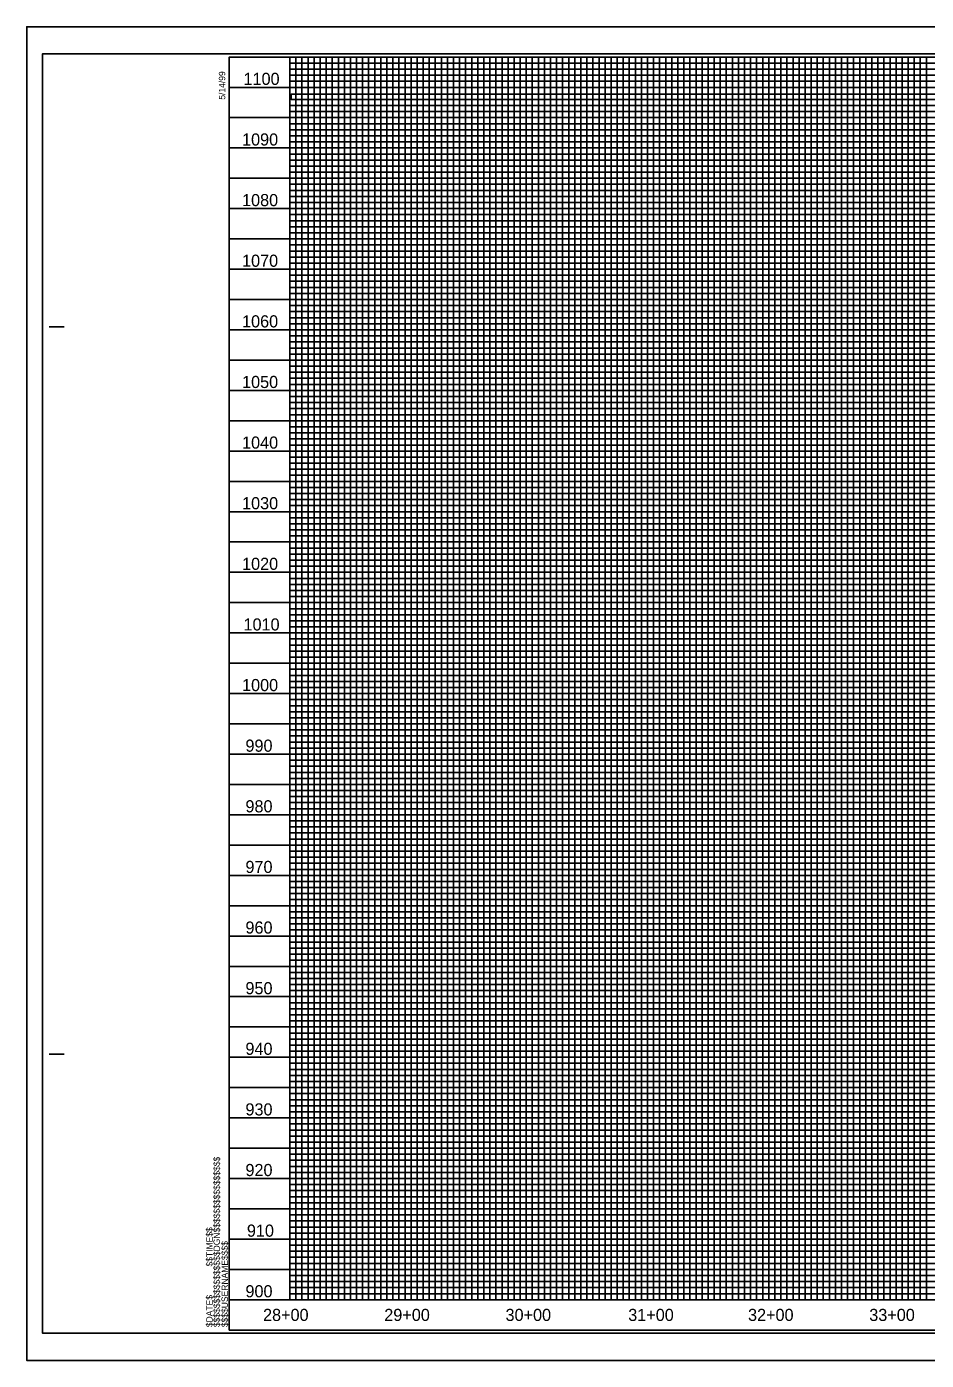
# Model space of a CAD drawing. Extents: x 1262239 to 1263984, y 747221 to 748321.
# Drawn here: x 1262239 to 1262981, y 747221 to 748321 of the extents above; entities that cross this region are included whole.
import ezdxf

# ---------------------------------------------------------------- set-up
doc = ezdxf.new("R2010")
doc.units = 0
for name, color, linetype in [('Pattern 1', 7, 'Continuous'), ('Pattern 2', 7, 'Continuous'), ('Prop Drainage Structure Bridge Opening', 7, 'Continuous'), ('Prop Grid Mask', 7, 'Continuous'), ('Prop Horizontal Alignment Curve and Spiral Data', 7, 'Continuous'), ('Prop Paved Shoulder', 7, 'Continuous'), ('Prop PFL Text', 7, 'Continuous'), ('Prop Roadway Bridge', 7, 'Continuous'), ('Prop Terminator CELL', 7, 'Continuous'), ('Prop Vertical Profile Strip Grade', 7, 'Continuous'), ('Prop VPI Label', 7, 'Continuous'), ('Sheet Sticker Exception Certification CELL', 7, 'Continuous')]:
    doc.layers.add(name, color=color, linetype=linetype)

msp = doc.modelspace()

# ---------------------------------------------------------------- linework, layer by layer
at = {"layer": 'Pattern 1'}
for points in [[(1262405.8, 748295.7), (1262455.8, 748295.7), (1262455.8, 747270.7), (1262505.8, 747270.7), (1262505.8, 748295.7), (1262555.8, 748295.7), (1262555.8, 747270.7), (1262605.8, 747270.7), (1262605.8, 748295.7), (1262655.8, 748295.7), (1262655.8, 747270.7), (1262705.8, 747270.7), (1262705.8, 748295.7), (1262755.8, 748295.7), (1262755.8, 747270.7), (1262805.8, 747270.7), (1262805.8, 748295.7), (1262855.8, 748295.7), (1262855.8, 747270.7), (1262905.8, 747270.7), (1262905.8, 748295.7), (1262955.8, 748295.7), (1262955.8, 747270.7), (1263005.8, 747270.7)], [(1263705.7, 748220.7), (1262405.9, 748220.7), (1262405.9, 748270.7), (1263605.8, 748270.7)], [(1263905.8, 748120.7), (1262405.8, 748120.7), (1262405.8, 748170.7), (1263705.7, 748170.7)], [(1263905.8, 748020.7), (1262405.8, 748020.7), (1262405.8, 748070.7), (1263905.8, 748070.7)], [(1263905.8, 747920.7), (1262405.8, 747920.7), (1262405.8, 747970.7), (1263905.8, 747970.7)], [(1263905.8, 747820.7), (1262405.8, 747820.7), (1262405.8, 747870.7), (1263905.8, 747870.7)], [(1263905.8, 747720.7), (1262405.8, 747720.7), (1262405.8, 747770.7), (1263905.8, 747770.7)], [(1263905.8, 747620.7), (1262405.8, 747620.7), (1262405.8, 747670.7), (1263905.8, 747670.7)], [(1263905.8, 747520.7), (1262405.8, 747520.7), (1262405.8, 747570.7), (1263905.8, 747570.7)], [(1263905.8, 747420.7), (1262405.8, 747420.7), (1262405.8, 747470.7), (1263905.8, 747470.7)], [(1263905.8, 747320.7), (1262405.8, 747320.7), (1262405.8, 747370.7), (1263905.8, 747370.7)]]:
    msp.add_lwpolyline(points, dxfattribs=at)
at = {"layer": 'Pattern 2'}
for points in [[(1262480.8, 747270.7), (1262480.8, 748295.7), (1262530.8, 748295.7), (1262530.8, 747270.7), (1262580.8, 747270.7), (1262580.8, 748295.7), (1262630.8, 748295.7), (1262630.8, 747270.7), (1262680.8, 747270.7), (1262680.8, 748295.7), (1262730.8, 748295.7), (1262730.8, 747270.7), (1262780.8, 747270.7), (1262780.8, 748295.7), (1262830.8, 748295.7), (1262830.8, 747270.7), (1262880.8, 747270.7), (1262880.8, 748295.7), (1262930.8, 748295.7), (1262930.8, 747270.7), (1262980.8, 747270.7), (1262980.8, 748295.7), (1263030.8, 748295.7)], [(1262405.8, 748245.7), (1263705.7, 748245.7)], [(1263705.7, 748195.7), (1262405.8, 748195.7), (1262405.8, 748145.7), (1263705.7, 748145.7)], [(1263905.8, 748095.7), (1262405.8, 748095.7), (1262405.8, 748045.7), (1263905.8, 748045.7)], [(1263905.8, 747995.7), (1262405.8, 747995.7), (1262405.8, 747945.7), (1263905.8, 747945.7)], [(1263905.8, 747895.7), (1262405.8, 747895.7), (1262405.8, 747845.7), (1263905.8, 747845.7)], [(1263905.8, 747795.7), (1262405.8, 747795.7), (1262405.8, 747745.7), (1263905.8, 747745.7)], [(1263905.8, 747695.7), (1262405.8, 747695.7), (1262405.8, 747645.7), (1263905.8, 747645.7)], [(1263905.8, 747595.7), (1262405.8, 747595.7), (1262405.8, 747545.7), (1263905.8, 747545.7)], [(1263905.8, 747495.7), (1262405.8, 747495.7), (1262405.8, 747445.7), (1263905.8, 747445.7)], [(1263905.8, 747395.7), (1262405.8, 747395.7), (1262405.8, 747345.7), (1263905.8, 747345.7)], [(1263905.8, 747295.7), (1262405.8, 747295.7)]]:
    msp.add_lwpolyline(points, dxfattribs=at)
at = {"layer": 'Prop Drainage Structure Bridge Opening'}
for p, q in [((1263922.8, 748320.7), (1262238.8, 748320.7)), ((1262238.8, 748320.7), (1262238.8, 747220.7)), ((1262238.8, 747220.7), (1263922.8, 747220.7))]:
    msp.add_line(p, q, dxfattribs=at)
at = {"layer": 'Prop Grid Mask'}
msp.add_lwpolyline([(1262455.8, 748295.7), (1263705.7, 748295.7), (1263705.7, 748134.7), (1263855.8, 748134.7), (1263855.8, 747270.7), (1262455.8, 747270.7)], close=True, dxfattribs=at)
at = {"layer": 'Prop Paved Shoulder'}
for p, q in [((1262257.3, 748073.2), (1262269.8, 748073.2)), ((1262257.3, 747473.2), (1262269.8, 747473.2)), ((1263905.8, 747270.7), (1262405.8, 747270.7)), ((1262405.8, 747245.7), (1262405.8, 747245.7)), ((1262405.8, 747245.7), (1262405.8, 747245.7)), ((1262405.8, 747245.7), (1262405.8, 747245.7)), ((1262405.8, 747245.7), (1262405.8, 747245.7)), ((1262405.8, 747245.7), (1262405.8, 747245.7)), ((1262405.8, 747245.7), (1262405.8, 747245.7))]:
    msp.add_line(p, q, dxfattribs=at)
msp.add_lwpolyline([(1263905.8, 748295.7), (1262405.8, 748295.7), (1262405.8, 747245.7), (1263905.8, 747245.7)], close=True, dxfattribs=at)
msp.add_lwpolyline([(1262443.3, 747245.7), (1262443.3, 747245.7)], dxfattribs=at)
at = {"layer": 'Prop PFL Text'}
for p, q in [((1262455.8, 748295.7), (1262455.8, 747270.7)), ((1262505.8, 748295.7), (1262505.8, 747270.7)), ((1262555.8, 748295.7), (1262555.8, 747270.7)), ((1262605.8, 748295.7), (1262605.8, 747270.7)), ((1262655.8, 748295.7), (1262655.8, 747270.7)), ((1262705.8, 748295.7), (1262705.8, 747270.7)), ((1262755.8, 748295.7), (1262755.8, 747270.7)), ((1262805.8, 748295.7), (1262805.8, 747270.7)), ((1262855.8, 748295.7), (1262855.8, 747270.7)), ((1262905.8, 748295.7), (1262905.8, 747270.7)), ((1262955.8, 748295.7), (1262955.8, 747270.7)), ((1262405.8, 748270.7), (1263605.8, 748270.7)), ((1262405.8, 748220.7), (1263705.7, 748220.7)), ((1262405.8, 748170.7), (1263705.7, 748170.7)), ((1262405.8, 748120.7), (1263905.8, 748120.7)), ((1262405.8, 748070.7), (1263905.8, 748070.7)), ((1262405.8, 748020.7), (1263905.8, 748020.7)), ((1262405.8, 747970.7), (1263905.8, 747970.7)), ((1262405.8, 747920.7), (1263905.8, 747920.7)), ((1262405.8, 747870.7), (1263905.8, 747870.7)), ((1262405.8, 747820.7), (1263905.8, 747820.7)), ((1262405.8, 747770.7), (1263905.8, 747770.7)), ((1262405.8, 747720.7), (1263905.8, 747720.7)), ((1262405.8, 747670.7), (1263905.8, 747670.7)), ((1262405.8, 747620.7), (1263905.8, 747620.7)), ((1262405.8, 747570.7), (1263905.8, 747570.7)), ((1262405.8, 747520.7), (1263905.8, 747520.7)), ((1262405.8, 747470.7), (1263905.8, 747470.7)), ((1262405.8, 747420.7), (1263905.8, 747420.7)), ((1262405.8, 747370.7), (1263905.8, 747370.7)), ((1262405.8, 747320.7), (1263905.8, 747320.7))]:
    msp.add_line(p, q, dxfattribs=at)
at = {"layer": 'Prop Roadway Bridge'}
msp.add_line((1262405.8, 747245.7), (1262405.8, 747245.7), dxfattribs=at)
at = {"layer": 'Prop Terminator CELL'}
msp.add_lwpolyline([(1263918.3, 748298.3), (1262251.8, 748298.3), (1262251.8, 747243.2), (1263918.3, 747243.2)], close=True, dxfattribs=at)
at = {"layer": 'Prop VPI Label'}
msp.add_lwpolyline([(1263922.8, 748320.7), (1262238.8, 748320.7), (1262238.8, 747220.7), (1263922.8, 747220.7)], close=True, dxfattribs=at)
at = {"layer": 'Sheet Sticker Exception Certification CELL'}
for p, q in [((1263855.8, 748115.7), (1262455.8, 748115.7)), ((1262455.8, 748115.7), (1262455.8, 748110.7)), ((1262455.8, 748110.7), (1263855.8, 748110.7)), ((1263855.8, 748090.7), (1262455.8, 748090.7))]:
    msp.add_line(p, q, dxfattribs=at)
for points in [[(1262460.8, 748295.7), (1262465.8, 748295.7), (1262470.8, 748295.7), (1262475.8, 748295.7), (1262485.8, 748295.7), (1262452.7, 748295.7), (1262457.7, 748295.7), (1262415.8, 748295.7), (1262420.8, 748295.7), (1262425.8, 748295.7), (1262435.8, 748295.7), (1262440.8, 748295.7), (1262445.8, 748295.7), (1262450.8, 748295.7), (1262460.8, 748295.7), (1262460.8, 747270.7), (1262465.8, 747270.7), (1262465.8, 748295.7), (1262470.8, 748295.7), (1262470.8, 747270.7), (1262475.8, 747270.7), (1262475.8, 748295.7), (1262485.8, 748295.7), (1262485.8, 747270.7), (1262490.8, 747270.7), (1262490.8, 748295.7), (1262495.8, 748295.7), (1262495.8, 747270.7), (1262500.8, 747270.7), (1262500.8, 748295.7), (1262510.8, 748295.7), (1262510.8, 747270.7), (1262515.8, 747270.7), (1262515.8, 748295.7), (1262520.8, 748295.7), (1262520.8, 747270.7), (1262525.8, 747270.7), (1262525.8, 748295.7), (1262535.8, 748295.7), (1262535.8, 747270.7), (1262540.8, 747270.7), (1262540.8, 748295.7), (1262545.8, 748295.7), (1262545.8, 747270.7), (1262550.8, 747270.7), (1262550.8, 748295.7), (1262560.8, 748295.7), (1262560.8, 747270.7), (1262565.8, 747270.7), (1262565.8, 748295.7), (1262570.8, 748295.7), (1262570.8, 747270.7), (1262575.8, 747270.7), (1262575.8, 748295.7), (1262585.8, 748295.7), (1262585.8, 747270.7), (1262590.8, 747270.7), (1262590.8, 748295.7), (1262595.8, 748295.7), (1262595.8, 747270.7), (1262600.8, 747270.7), (1262600.8, 748295.7), (1262610.8, 748295.7), (1262610.8, 747270.7), (1262615.8, 747270.7), (1262615.8, 748295.7), (1262620.8, 748295.7), (1262620.8, 747270.7)], [(1263605.8, 748290.7), (1262455.8, 748290.7), (1262455.8, 748285.7), (1263605.8, 748285.7)], [(1262620.8, 747270.7), (1262625.8, 747270.7), (1262625.8, 748295.7), (1262635.8, 748295.7), (1262635.8, 747270.7), (1262640.8, 747270.7), (1262640.8, 748295.7), (1262645.8, 748295.7), (1262645.8, 747270.7), (1262650.8, 747270.7), (1262650.8, 748295.7), (1262660.8, 748295.7), (1262660.8, 747270.7), (1262665.8, 747270.7), (1262665.8, 748295.7), (1262665.8, 748295.7), (1262670.8, 748295.7), (1262670.8, 747270.7), (1262675.8, 747270.7), (1262675.8, 748295.7), (1262685.8, 748295.7), (1262685.8, 747270.7), (1262690.8, 747270.7), (1262690.8, 748295.7), (1262695.8, 748295.7), (1262695.8, 747270.7), (1262700.8, 747270.7), (1262700.8, 748295.7), (1262710.8, 748295.7), (1262710.8, 747270.7), (1262715.8, 747270.7), (1262715.8, 748295.7), (1262720.8, 748295.7), (1262720.8, 747270.7), (1262725.8, 747270.7), (1262725.8, 748295.7), (1262735.8, 748295.7), (1262735.8, 747270.7), (1262740.8, 747270.7), (1262740.8, 748295.7), (1262745.8, 748295.7), (1262745.8, 747270.7), (1262750.8, 747270.7), (1262750.8, 748295.7), (1262760.8, 748295.7), (1262760.8, 747270.7), (1262765.8, 747270.7), (1262765.8, 748295.7), (1262770.8, 748295.7), (1262770.8, 747270.7), (1262775.8, 747270.7), (1262775.8, 748295.7), (1262785.8, 748295.7), (1262785.8, 747270.7), (1262800.8, 747270.7), (1262800.8, 748295.7), (1262810.8, 748295.7), (1262810.8, 747270.7), (1262815.8, 747270.7), (1262815.8, 748295.7), (1262820.8, 748295.7), (1262820.8, 747270.7), (1262825.8, 747270.7), (1262825.8, 748295.7), (1262835.8, 748295.7), (1262835.8, 747270.7), (1262840.8, 747270.7), (1262840.8, 748295.7), (1262845.8, 748295.7), (1262845.8, 747270.7), (1262850.8, 747270.7), (1262850.8, 748295.7), (1262860.8, 748295.7), (1262860.8, 747270.7), (1262865.8, 747270.7), (1262865.8, 748295.7), (1262870.8, 748295.7), (1262870.8, 747270.7), (1262875.8, 747270.7), (1262875.8, 748295.7), (1262885.8, 748295.7), (1262885.8, 747270.7), (1262890.8, 747270.7), (1262890.8, 748295.7), (1262895.8, 748295.7), (1262895.8, 747270.7), (1262900.8, 747270.7), (1262900.8, 748295.7), (1262910.8, 748295.7), (1262910.8, 747270.7), (1262915.8, 747270.7), (1262915.8, 748295.7), (1262920.8, 748295.7), (1262920.8, 747270.7), (1262925.8, 747270.7), (1262925.8, 748295.7), (1262935.8, 748295.7), (1262935.8, 747270.7)], [(1262790.8, 748295.7), (1262790.8, 747270.7), (1262795.8, 747270.7), (1262795.8, 748295.7)], [(1262790.8, 748295.1), (1262790.8, 747270.7), (1262795.8, 747270.7), (1262795.8, 748295.1)], [(1262940.8, 748295.7), (1262940.8, 747270.7), (1262945.8, 747270.7), (1262945.8, 748295.7), (1262950.8, 748295.7), (1262950.8, 747270.7), (1262960.8, 747270.7), (1262960.8, 748295.7), (1262965.8, 748295.7), (1262965.8, 747270.7), (1262970.8, 747270.7), (1262970.8, 748295.7), (1262975.8, 748295.7), (1262975.8, 747270.7)], [(1263605.8, 748280.7), (1262455.8, 748280.7), (1262455.8, 748275.7), (1263605.8, 748275.7)], [(1263605.8, 748265), (1262456.8, 748265), (1262456.8, 748260.7), (1263605.8, 748260.7)], [(1263605.8, 748255.7), (1262455.8, 748255.7), (1262455.8, 748250.7), (1263605.8, 748250.7)], [(1263705.7, 748240.7), (1262455.8, 748240.7), (1262455.8, 748235.7), (1263705.7, 748235.7)], [(1263705.7, 748230.7), (1262455.8, 748230.7), (1262455.8, 748225.7), (1263705.7, 748225.7)], [(1263705.7, 748215.7), (1262455.8, 748215.7), (1262455.8, 748210.7), (1263705.7, 748210.7)], [(1263705.7, 748205.7), (1262455.8, 748205.7), (1262455.8, 748200.7), (1263705.7, 748200.7)], [(1263705.7, 748190.7), (1262455.8, 748190.7), (1262455.8, 748185.7), (1263705.7, 748185.7)], [(1263705.7, 748180.7), (1262455.8, 748180.7), (1262455.8, 748175.7), (1263705.7, 748175.7)], [(1263705.7, 748165.7), (1262455.8, 748165.7), (1262455.8, 748160.7), (1263705.7, 748160.7)], [(1263705.7, 748155.7), (1262455.8, 748155.7), (1262455.8, 748155.7), (1262455.8, 748135.7), (1263705.7, 748135.7)], [(1262455.8, 748150.7), (1263705.7, 748150.7)], [(1263705.7, 748140.7), (1262455.8, 748140.7)], [(1263855.8, 748130.7), (1262455.8, 748130.7), (1262455.8, 748125.7), (1263855.8, 748125.7)], [(1263855.8, 748105.7), (1262455.8, 748105.7), (1262455.8, 748100.7), (1263855.8, 748100.7)], [(1263855.8, 748085.7), (1262455.8, 748085.7), (1262455.8, 748080.7), (1263855.8, 748080.7)], [(1263855.8, 748075.7), (1262455.8, 748075.7)], [(1262455.8, 748065.7), (1263855.8, 748065.7)], [(1263855.8, 748060.7), (1262455.8, 748060.7), (1262455.8, 748055.7), (1263855.8, 748055.7)], [(1263855.8, 748050.7), (1262455.8, 748050.7), (1262455.8, 748040.7), (1263855.8, 748040.7)], [(1263855.8, 748035.7), (1262455.8, 748035.7), (1262455.8, 748030.7), (1263855.8, 748030.7)], [(1263855.8, 748025.7), (1262455.8, 748025.7), (1262455.8, 748015.7), (1263855.8, 748015.7)], [(1263855.8, 748010.7), (1262455.8, 748010.7), (1262455.8, 748005.7), (1263855.8, 748005.7)], [(1263855.8, 748000.7), (1262455.8, 748000.7), (1262455.8, 747990.7), (1263855.8, 747990.7)], [(1263855.8, 747985.7), (1262455.8, 747985.7), (1262455.8, 747980.7), (1263855.8, 747980.7)], [(1263855.8, 747975.7), (1262455.8, 747975.7), (1262455.8, 747965.7), (1263855.8, 747965.7)], [(1263855.8, 747960.7), (1262455.8, 747960.7), (1262455.8, 747955.7), (1263855.8, 747955.7)], [(1263855.8, 747950.7), (1262455.8, 747950.7), (1262455.8, 747940.7), (1263855.8, 747940.7)], [(1263855.8, 747935.7), (1262455.8, 747935.7), (1262455.8, 747930.7), (1263855.8, 747930.7)], [(1263855.8, 747925.7), (1262455.8, 747925.7), (1262455.8, 747915.7), (1263855.8, 747915.7)], [(1263855.8, 747910.7), (1262455.8, 747910.7), (1262455.8, 747905.7), (1263855.8, 747905.7)], [(1263855.8, 747900.7), (1262455.8, 747900.7), (1262455.8, 747890.7), (1263855.8, 747890.7)], [(1263855.8, 747885.7), (1262455.8, 747885.7), (1262455.8, 747880.7), (1263855.8, 747880.7)], [(1263855.8, 747875.7), (1262455.8, 747875.7), (1262455.8, 747865.7), (1263855.8, 747865.7)], [(1263855.8, 747860.7), (1262455.8, 747860.7), (1262455.8, 747855.7), (1263855.8, 747855.7)], [(1263855.8, 747850.7), (1262455.8, 747850.7), (1262455.8, 747840.7), (1263855.8, 747840.7)], [(1263855.8, 747835.7), (1262455.8, 747835.7), (1262455.8, 747830.7), (1263855.8, 747830.7)], [(1263855.8, 747825.7), (1262455.8, 747825.7), (1262455.8, 747815.7), (1263855.8, 747815.7)], [(1263855.8, 747810.7), (1262455.8, 747810.7), (1262455.8, 747805.7), (1263855.8, 747805.7)], [(1263855.8, 747800.7), (1262455.8, 747800.7), (1262455.8, 747790.7), (1263855.8, 747790.7)], [(1263855.8, 747785.7), (1262455.8, 747785.7), (1262455.8, 747780.7), (1263855.8, 747780.7)], [(1263855.8, 747775.7), (1262455.8, 747775.7)], [(1262455.8, 747765.7), (1263855.8, 747765.7)], [(1263855.8, 747760.7), (1262455.8, 747760.7), (1262455.8, 747755.7), (1263855.8, 747755.7)], [(1263855.8, 747750.7), (1262455.8, 747750.7), (1262455.8, 747740.7), (1263855.8, 747740.7)], [(1263855.8, 747735.7), (1262455.8, 747735.7), (1262455.8, 747730.7), (1263855.8, 747730.7)], [(1263855.8, 747725.7), (1262455.8, 747725.7), (1262455.8, 747715.7), (1263855.8, 747715.7)], [(1263855.8, 747710.7), (1262455.8, 747710.7), (1262455.8, 747705.7), (1263855.8, 747705.7)], [(1263855.8, 747700.7), (1262455.8, 747700.7), (1262455.8, 747690.7), (1263855.8, 747690.7)], [(1263855.8, 747685.7), (1262455.8, 747685.7), (1262455.8, 747680.7), (1263855.8, 747680.7)], [(1263855.8, 747675.7), (1262455.8, 747675.7), (1262455.8, 747665.7), (1263855.8, 747665.7)], [(1263855.8, 747660.7), (1262455.8, 747660.7), (1262455.8, 747655.7), (1263855.8, 747655.7)], [(1263855.8, 747650.7), (1262455.8, 747650.7), (1262455.8, 747640.7), (1263855.8, 747640.7)], [(1263855.8, 747635.7), (1262455.8, 747635.7), (1262455.8, 747630.7), (1263855.8, 747630.7)], [(1263855.8, 747625.7), (1262455.8, 747625.7), (1262455.8, 747615.7), (1263855.8, 747615.7)], [(1263855.8, 747610.7), (1262455.8, 747610.7), (1262455.8, 747605.7), (1263855.8, 747605.7)], [(1263855.8, 747600.7), (1262455.8, 747600.7), (1262455.8, 747590.7), (1263855.8, 747590.7)], [(1263855.8, 747585.7), (1262455.8, 747585.7), (1262455.8, 747580.7), (1263855.8, 747580.7)], [(1263855.8, 747575.7), (1262455.8, 747575.7), (1262455.8, 747565.7), (1263855.8, 747565.7)], [(1263855.8, 747560.7), (1262455.8, 747560.7), (1262455.8, 747555.7), (1263855.8, 747555.7)], [(1263855.8, 747550.7), (1262455.8, 747550.7), (1262455.8, 747540.7), (1263855.8, 747540.7)], [(1263855.8, 747535.7), (1262455.8, 747535.7), (1262455.8, 747530.7), (1263855.8, 747530.7)], [(1263855.8, 747525.7), (1262455.8, 747525.7), (1262455.8, 747515.7), (1263855.8, 747515.7)], [(1263855.8, 747510.7), (1262455.8, 747510.7), (1262455.8, 747505.7), (1263855.8, 747505.7)], [(1263855.8, 747500.7), (1262455.8, 747500.7), (1262455.8, 747490.7), (1263855.8, 747490.7)], [(1263855.8, 747485.7), (1262455.8, 747485.7), (1262455.8, 747480.7), (1263855.8, 747480.7)], [(1263855.8, 747475.7), (1262455.8, 747475.7)], [(1262455.8, 747465.7), (1263855.8, 747465.7)], [(1263855.8, 747460.7), (1262455.8, 747460.7), (1262455.8, 747455.7), (1263855.8, 747455.7)], [(1263855.8, 747450.7), (1262455.8, 747450.7)], [(1262455.8, 747440.7), (1263855.8, 747440.7)], [(1263855.8, 747435.7), (1262455.8, 747435.7), (1262455.8, 747430.7), (1263855.8, 747430.7)], [(1263855.8, 747425.7), (1262455.8, 747425.7), (1262455.8, 747415.7), (1263855.8, 747415.7)], [(1263855.8, 747410.7), (1262455.8, 747410.7), (1262455.8, 747405.7), (1263855.8, 747405.7)], [(1263855.8, 747400.7), (1262455.8, 747400.7), (1262455.8, 747390.7), (1263855.8, 747390.7)], [(1263855.8, 747385.7), (1262455.8, 747385.7), (1262455.8, 747380.7), (1263855.8, 747380.7)], [(1263855.8, 747375.7), (1262455.8, 747375.7), (1262455.8, 747365.7), (1263855.8, 747365.7)], [(1263855.8, 747360.7), (1262455.8, 747360.7), (1262455.8, 747355.7), (1263855.8, 747355.7)], [(1263855.8, 747350.7), (1262455.8, 747350.7), (1262455.8, 747340.7), (1263855.8, 747340.7)], [(1263855.8, 747335.7), (1262455.8, 747335.7), (1262455.8, 747330.7), (1263855.8, 747330.7)], [(1263855.8, 747325.7), (1262455.8, 747325.7), (1262455.8, 747315.7), (1263855.8, 747315.7)], [(1263855.8, 747310.7), (1262455.8, 747310.7), (1262455.8, 747305.7), (1263855.8, 747305.7)], [(1263855.8, 747300.7), (1262455.8, 747300.7), (1262455.8, 747290.7), (1263855.8, 747290.7)], [(1263855.8, 747285.7), (1262455.8, 747285.7), (1262455.8, 747280.7), (1263855.8, 747280.7)], [(1263855.8, 747275.7), (1262455.8, 747275.7)]]:
    msp.add_lwpolyline(points, dxfattribs=at)

# ---------------------------------------------------------------- texts
at = {"layer": 'Prop Horizontal Alignment Curve and Spiral Data'}
for s, p in [('28+00', (1262433.7, 747253.2)), ('29+00', (1262533.7, 747253.2)), ('30+00', (1262633.7, 747253.2)), ('31+00', (1262734.9, 747253.2)), ('32+00', (1262833.7, 747253.2)), ('33+00', (1262933.7, 747253.2))]:
    msp.add_text(s, height=10, dxfattribs=at).set_placement(p)
at = {"layer": 'Prop Paved Shoulder'}
msp.add_text('5/14/99', height=5.25, rotation=90, dxfattribs=at).set_placement((1262402.5, 748260.5))
at = {"layer": 'Prop Roadway Bridge'}
for s, p in [('$$$$$$$$$$$$$$$$DGN$$$$$$$$$$$$$$$$', (1262398.1, 747248.1)), ('$$TIME$$', (1262392.1, 747298.1)), ('$$$$USERNAME$$$$', (1262404.7, 747248.1)), ('$DATE$', (1262392.1, 747248.1))]:
    msp.add_text(s, height=5.25, rotation=90, dxfattribs=at).set_placement(p)
at = {"layer": 'Prop Vertical Profile Strip Grade'}
for s, p in [('1100', (1262417.6, 748272.7)), ('1090', (1262416.4, 748222.7)), ('1080', (1262416.4, 748172.7)), ('1070', (1262416.4, 748122.7)), ('1060', (1262416.4, 748072.7)), ('1050', (1262416.4, 748022.7)), ('1040', (1262416.4, 747972.7)), ('1030', (1262416.4, 747922.7)), ('1020', (1262416.4, 747872.7)), ('1010', (1262417.6, 747822.7)), ('1000', (1262416.4, 747772.7)), ('990', (1262419.2, 747722.7)), ('980', (1262419.2, 747672.7)), ('970', (1262419.2, 747622.7)), ('960', (1262419.2, 747572.7)), ('950', (1262419.2, 747522.7)), ('940', (1262419.2, 747472.7)), ('930', (1262419.2, 747422.7)), ('920', (1262419.2, 747372.7)), ('910', (1262420.4, 747322.7)), ('900', (1262419.2, 747272.7))]:
    msp.add_text(s, height=10, dxfattribs=at).set_placement(p)

doc.saveas('drawing.dxf')
